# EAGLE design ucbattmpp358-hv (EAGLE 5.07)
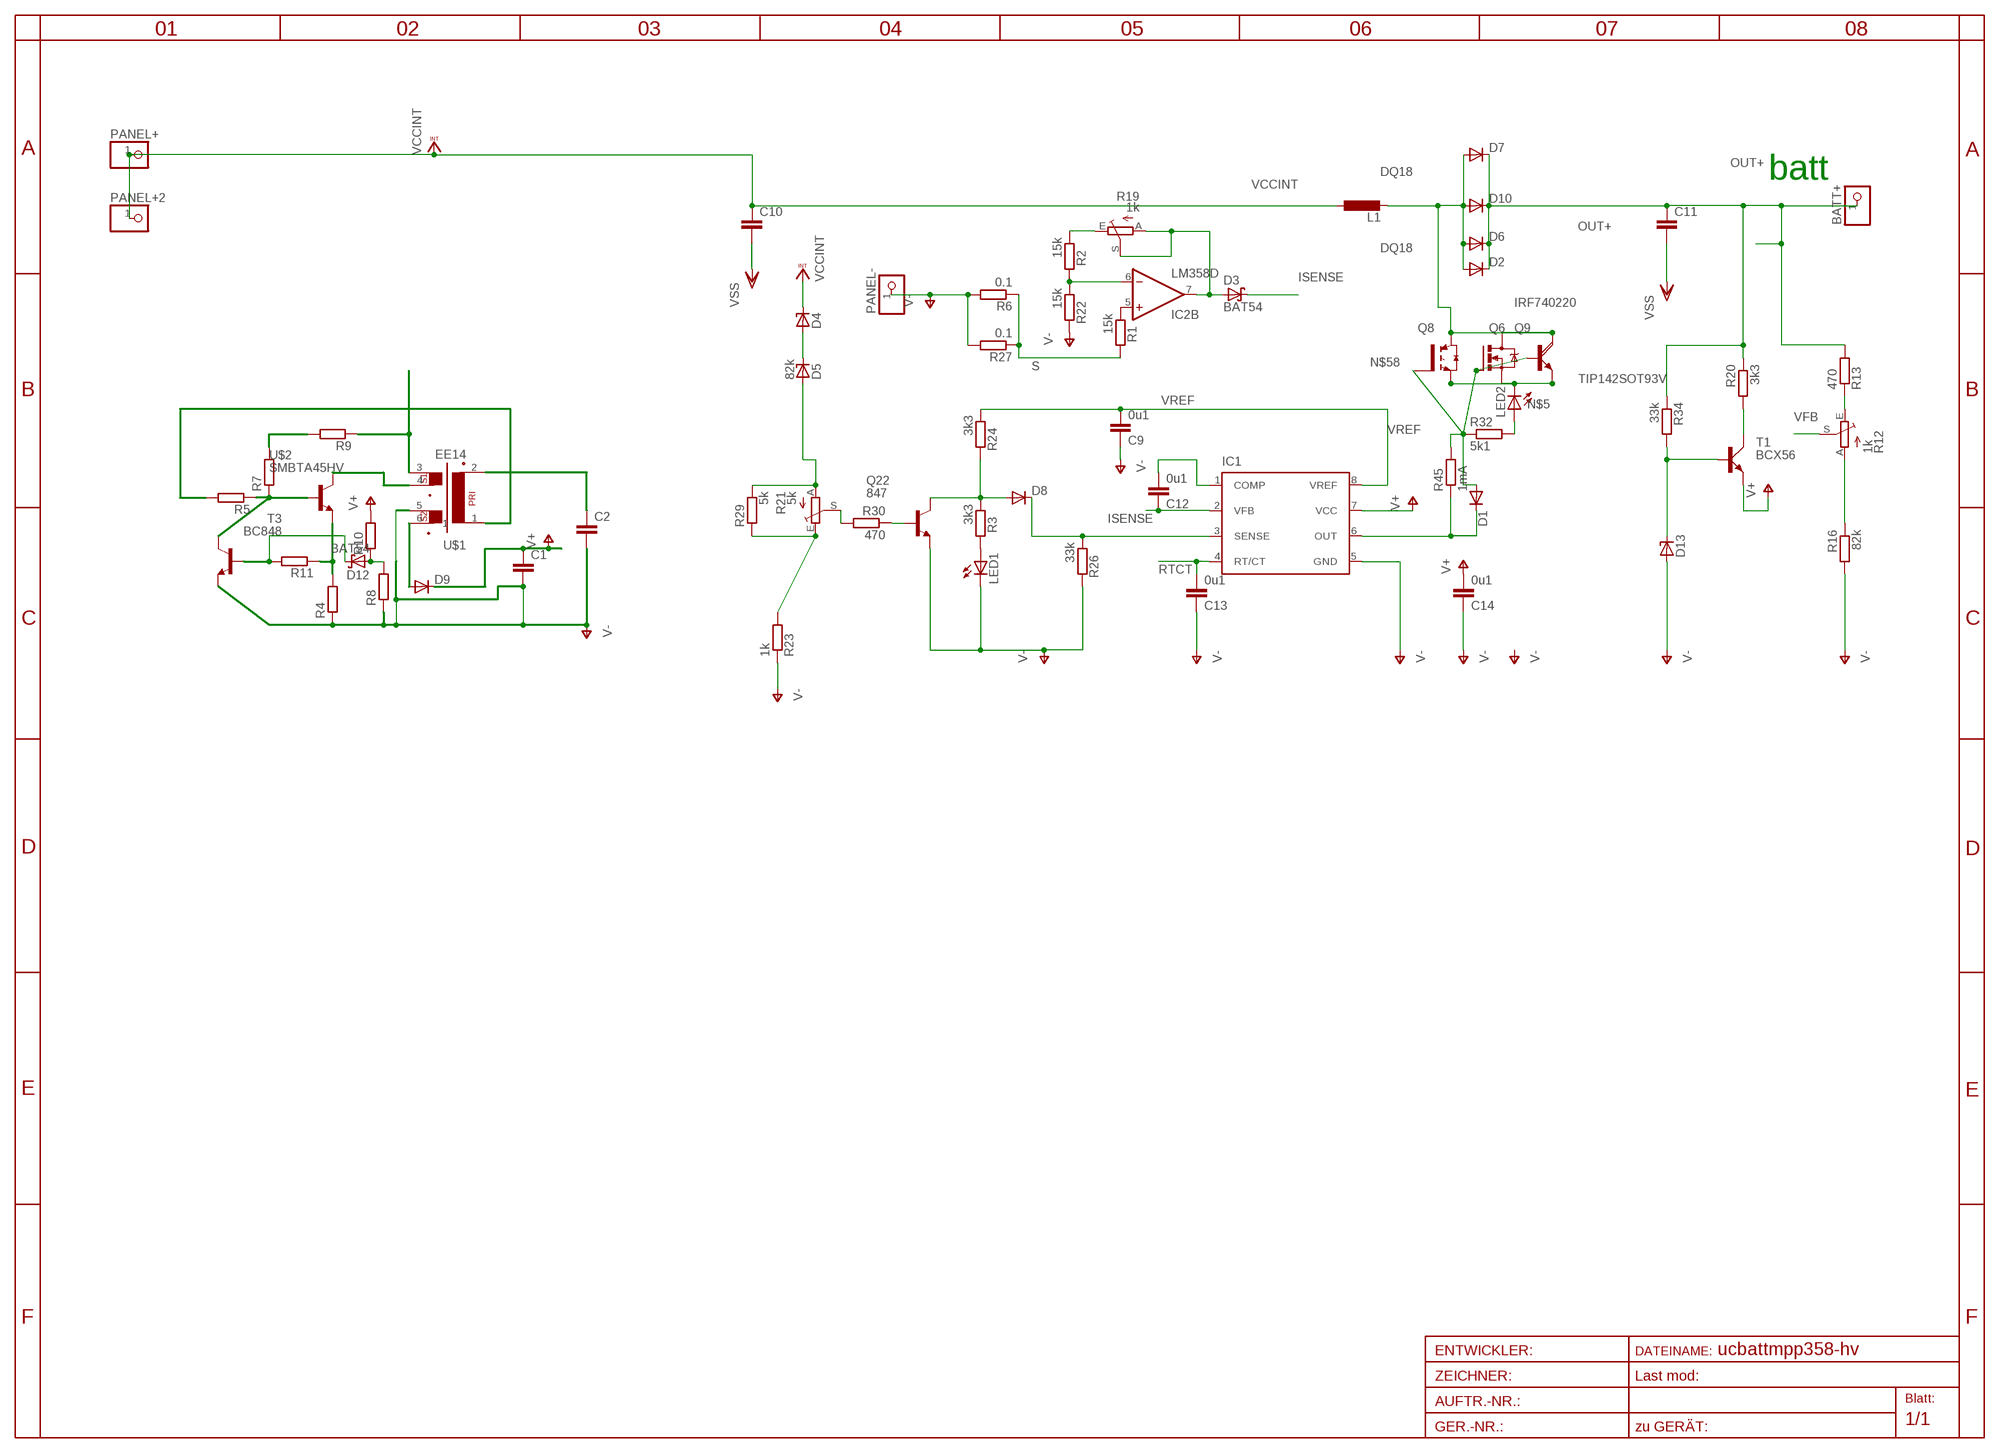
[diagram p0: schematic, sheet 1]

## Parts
BATT+  PINHD-1X12MM3  [1X2MM3]
C1  C-EUC1206  [C1206]
C2  C-EUC0805  [C0805]
C9  0u1  C-EUC1206  [C1206]
C10  C-EU075-052X106  [C075-052X106]
C11  C-EU075-052X106  [C075-052X106]
C12  0u1  C-EUC0805  [C0805]
C13  0u1  C-EUC1206  [C1206]
C14  0u1  C-EUC1206  [C1206]
D1  DIODE-MINIMELF  [MINIMELF]
D2  DIODE-SMC  [SMC]
D3  BAT54  [SOT23]
D4  ZENER-DIODESOD80C  [SOD80C]
D5  82k  ZENER-DIODESOD80C  [SOD80C]
D6  DIODE-SMC  [SMC]
D7  DIODE-SMC  [SMC]
D8  DIODE-MINIMELF  [MINIMELF]
D9  DIODE-SMA-DO214  [SMA-DO214AC]
D10  DIODE-SMC  [SMC]
D12  BAT54  [SOT23]
D13  ZENER-DIODESOD80C  [SOD80C]
IC1  UC1843D8  [SO-08]
IC2  LM358D  [SO08]
L1  L-EUOPEN6  [OPEN6_3]
LED1  LEDCHIPLED_1206  [CHIPLED_1206]
LED2  LEDCHIPLED_1206  [CHIPLED_1206]
PANEL+  PINHD-1X11MM6  [1X1MM8]
PANEL+2  PINHD-1X12MM3  [1X2MM3]
PANEL-  PINHD-1X12MM3  [1X2MM3]
Q6  IRF740220  [TO220BV]
Q8  IRG4BC15UD-S  [D2PACK]
Q9  TIP142SOT93V  [SOT93V]
Q22  847  BC847ASMD  [SOT23]
R1  15k  R-EU_R0805  [R0805]
R2  15k  R-EU_R0805  [R0805]
R3  3k3  R-EU_R0805  [R0805]
R4  R-EU_R0805  [R0805]
R5  R-EU_R0805  [R0805]
R6  0.1  R-EU_0207/10  [0207/10]
R7  R-EU_R1206  [R1206]
R8  R-EU_R0805  [R0805]
R9  R-EU_R1206  [R1206]
R10  R-EU_R0805  [R0805]
R11  R-EU_R0805  [R0805]
R12  1k  TRIM_EU-S64W  [S64W]
R13  470  R-EU_R0805  [R0805]
R16  82k  R-EU_R0805  [R0805]
R19  1k  TRIM_EU-S64W  [S64W]
R20  3k3  R-EU_R0805  [R0805]
R21  5k  TRIM_EU-S64W  [S64W]
R22  15k  R-EU_R0805  [R0805]
R23  1k  R-EU_R0805  [R0805]
R24  3k3  R-EU_R0805  [R0805]
R26  33k  R-EU_R0805  [R0805]
R27  0.1  R-EU_R3216  [R3216]
R29  5k  R-EU_R0805  [R0805]
R30  470  R-EU_R0805  [R0805]
R32  5k1  R-EU_R0805  [R0805]
R34  33k  R-EU_R0805  [R0805]
R45  1mA  R-EU_R0805  [R0805]
T1  BCX56  [SOT223]
T3  BC848  [SOT23]
U$1  EE14  [EE14]
U$2  SMBTA45HV  [SOT23HV]

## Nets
A: D9.A U$1.6
B1C2: R5.1 R7.1 T3.C U$2.1(B)
C1: U$1.4 U$2.3(C)
DQ18: D2.A D6.A D7.A D10.A L1.2 Q6.D Q8.2(C) Q9.C
EB: R4.2 R11.1 U$2.2(E)
ISENSE: D3.3(C) D8.C IC1.3(SENSE) R26.1
N$1: IC2.5(B:+IN) R1.1
N$2: R2.1 R19.E
N$3: Q22.1(B) R30.1
N$4: LED1.A R3.2
N$5: LED2.A R32.2
N$6: R5.2 U$1.1
N$7: C2.1 U$1.2
N$8: R7.2 R9.2
N$9: D12.3(C) R11.2 T3.B
N$10: D12.1(A) R8.2 R10.1
N$18: C12.2 IC1.1(COMP)
N$21: R12.A R16.1
N$22: D3.1(A) IC2.7(B:OUT) R19.A R19.S
N$23: R20.2 T1.2(C)
N$25: D1.C IC1.6(OUT) R45.1
N$26: D13.C R34.2 T1.1(B)
N$27: IC2.6(B:-IN) R2.2 R22.1
N$30: D4.A D5.C
N$32: D5.A R21.A R29.1
N$34: R21.E R23.2 R29.2
N$37: R12.E R13.1
N$58: D1.A Q6.G Q8.1(G) Q9.B R32.1 R45.2
N$71: D8.A Q22.3(C) R3.1 R24.2
OUT+: BATT+.1 C11.1 D2.C D6.C D7.C D10.C R9.1 R13.2 R20.1 R34.1 U$1.3
PRB1: R21.S R30.2
RTCT: C13.2 IC1.4(RT/CT)
S: LED2.C Q6.S Q8.3(E) Q9.E R1.2 R6.1 R27.1
V+: C1.1 C14.2 D9.K(C) IC1.7(VCC) R10.2 T1.3(E)
V-: C1.2 C2.2 C9.1 C10.2 C11.2 C13.1 C14.1 D13.A IC1.5(GND) LED1.C PANEL-.1 Q22.2(E) R4.1 R6.2 R8.1 R16.2 R22.2 R23.1 R26.2 R27.2 T3.E U$1.5 ; supply symbol labelled VSS
VCCINT: C10.1 D4.C L1.1 PANEL+2.1 PANEL+.1
VFB: C12.1 IC1.2(VFB) R12.S
VREF: C9.2 IC1.8(VREF) R24.1
Unconnected: IC2.1(A:OUT) IC2.2(A:-IN) IC2.3(A:+IN)

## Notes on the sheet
- batt

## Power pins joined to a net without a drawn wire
V+: IC2.8(P:V+)
V-: IC2.4(P:V-)

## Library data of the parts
BATT+ PANEL+ PANEL+2 PANEL- = pinhead:PINHD-1X1: PIN HEADER
C1 C2 C9-C14 = rcl:C-EU: CAPACITOR, European symbol
D1 D2 D6-D10 = diode:DIODE-: DIODE
D3 D12 = diode:BAT54: Schottky Diodes
D4 D5 D13 = diode:ZENER-DIODE: Z-Diode
IC1 = texas:UC1843D8: PULSE WIDTH MODULATOR
IC2 = linear:LM358: OP AMP also LM158; LM258; LM2904 Source: http://cache.national.com/ds/LM/LM158.pdf
L1 = rcl:L-EU: INDUCTOR, European symbol
LED1 LED2 = led:LED: LED
Q6 = transistor-power:IRF740: N-CHANNEL MOS FET
Q8 = transistor-power:IRG4BC15UD-: INSULATED GATE BIPOLAR TRANSISTOR WITH ULTRAFAST SOFT RECOVERY DIODE
Q9 = transistor-power:TIP142: NPN DARLINGTON TRANSISTOR
Q22 = transistor-npn:BC847*: NPN Transistor
R1-R11 R13 R16 R20 R22-R24 R26 R27 R29 R30 R34 = rcl:R-EU_: RESISTOR, European symbol
R12 R19 R21 = pot:TRIM_EU-: POTENTIOMETER
R32 R45 = rcl-2:R-EU_: RESISTOR, European symbol
T1 = transistor-power:BCX56
T3 = transistor:BC848: NPN TRANSISTOR
U$1 = trafo:EE14
U$2 = transistor-npn:SMBTA45

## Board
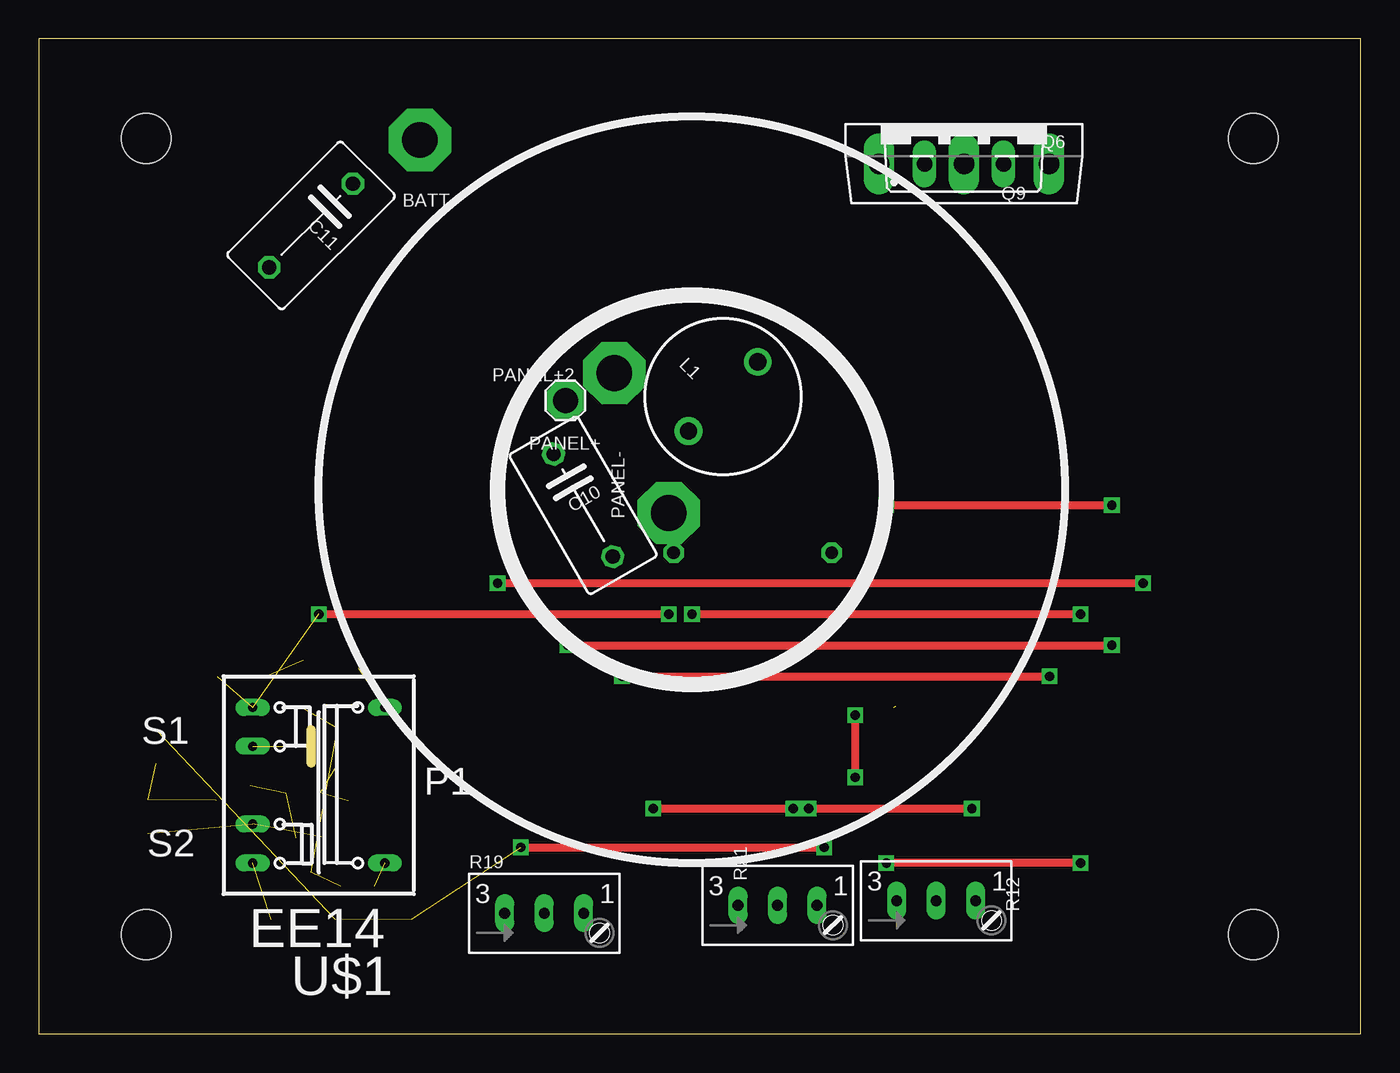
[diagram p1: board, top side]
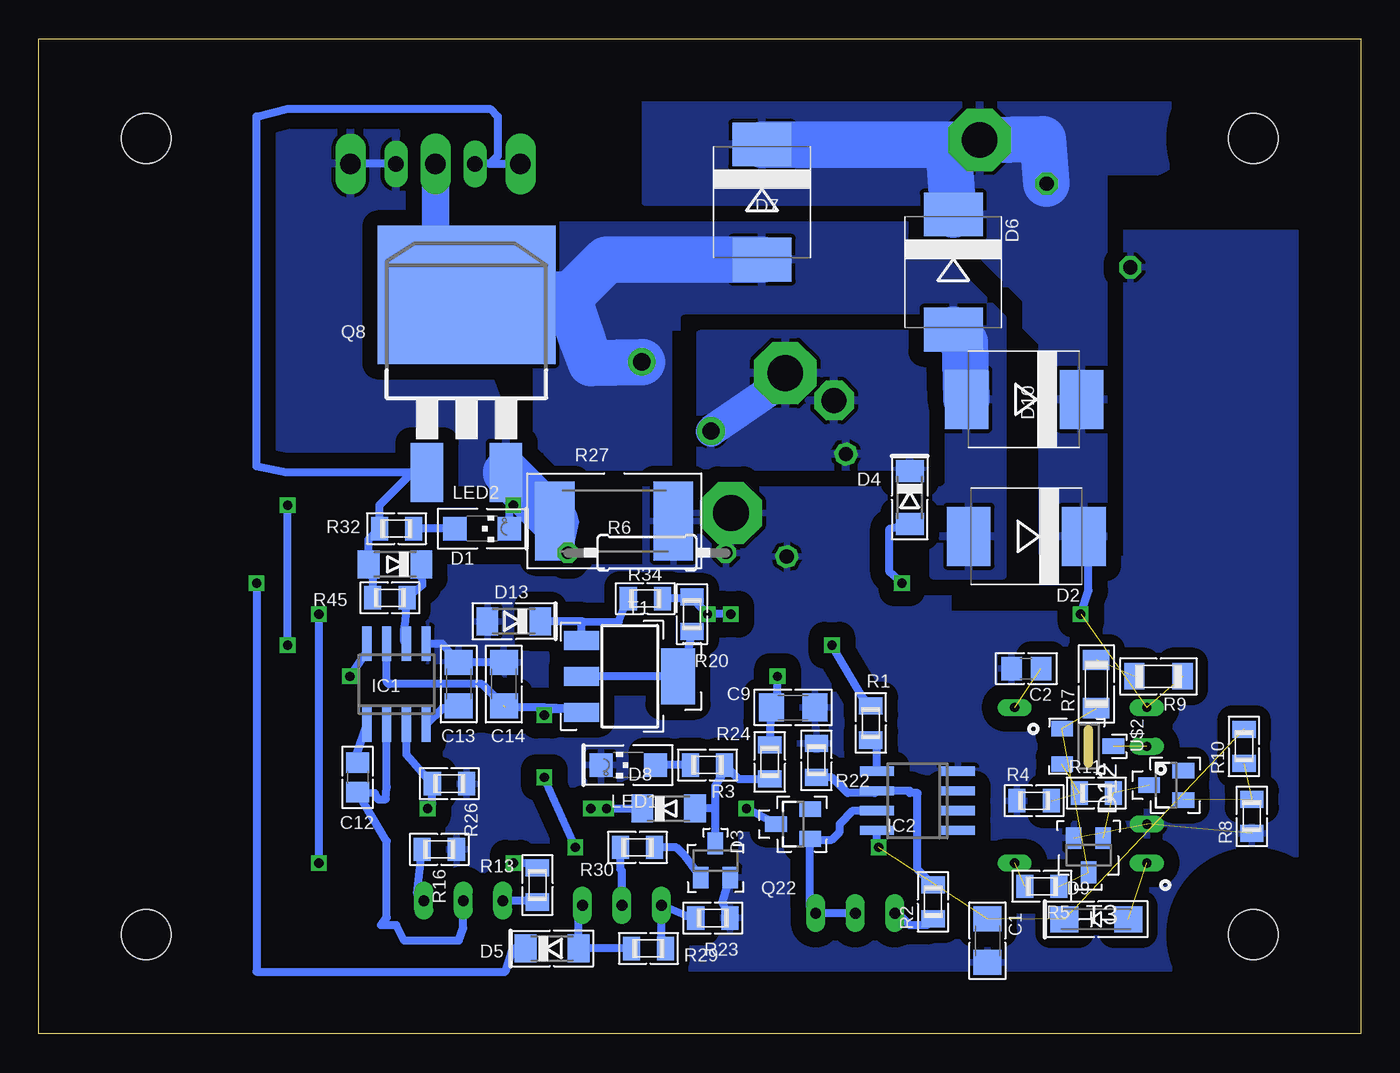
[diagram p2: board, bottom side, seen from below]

Size 85 x 64 mm. Coordinates in mm from the lower left corner, seen from the top.
Outline: 0,0 85,0 85,64 0,64 0,0
Copper layers (1*16): Top 0.035mm / dielectric 1.5mm / Bottom 0.035mm
Design rules "default *": minimum track width 10mil, minimum drill 24mil, track to track 8mil, track to pad 8mil, pad to pad 8mil, via to via 8mil, smd to smd 8mil, copper to edge 4mm, drill to drill 8mil, minimum pad ring 10mil, minimum via ring 8mil, stop-mask expansion 4mil, vias tented up to drill 0mil, thermal gap 10mil
Holes 3.2 mm at 6.9,57.6 6.9,6.4 78.1,6.4 78.1,57.6

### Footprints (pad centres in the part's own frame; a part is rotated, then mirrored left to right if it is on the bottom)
1X2MM3 = drill 2.3 pad 4 octagon: 1 0,0
C1206 = smd 1.6 x 1.8: 1 -1.4,0; 2 1.4,0
C0805 = smd 1.3 x 1.5: 1 -0.95,0; 2 0.95,0
C075-052X106 = drill 0.914 octagon: 1 -3.81,0; 2 3.81,0
MINIMELF = smd 1.4 x 1.8: A 1.7,0; C -1.7,0
SMC = smd 2.8 x 3.8: A 3.7,0; C -3.7,0
SOT23 = smd 1 x 1.4: 1 -0.95,-1.1; 2 0.95,-1.1; 3 0,1.1
SOD80C = smd 1.4 x 1.8: A 1.7,0; C -1.7,0
SMA-DO214AC = smd 1.8 x 1.7: A 2.05,-0.127; K -2.05,-0.127
SO-08 = smd 0.6 x 2.2: 1 -1.905,-2.6; 2 -0.635,-2.6; 3 0.635,-2.6; 4 1.905,-2.6; 5 1.905,2.6; 6 0.635,2.6; 7 -0.635,2.6; 8 -1.905,2.6
SO08 = smd 0.6 x 2.2: 1 -1.905,-2.6; 2 -0.635,-2.6; 3 0.635,-2.6; 4 1.905,-2.6; 5 1.905,2.6; 6 0.635,2.6; 7 -0.635,2.6; 8 -1.905,2.6
OPEN6_3 = drill 1.1 pad 1.778 round: 1 -3.15,0; 2 3.15,0
CHIPLED_1206 = smd 1.5 x 1.5: A 0,-1.75; C 0,1.75
1X1MM8 = drill 1.6 pad 2.54 octagon: 1 0,0
TO220BV = drill 1.016 long: D 0,-2.54; G -2.54,-2.54; S 2.54,-2.54
D2PACK = smd 2.083 x 3.81: 1 -2.54,-8.89; 3 2.54,-8.89 | smd 11.43 x 8.89: 2 0,2.54
SOT93V = drill 1.3 pad 1.676 long: B -5.461,-2.54; C 0,-2.54; E 5.461,-2.54
R0805 = smd 1.1 x 1.5: 1 -1.1,0; 2 1.1,0
0207/10 = drill 0.813 octagon: 1 -5.08,0; 2 5.08,0
R1206 = smd 1.3 x 1.7: 1 -1.55,0; 2 1.55,0
S64W = drill 0.7 long: A 2.54,1.27; E -2.54,1.27; S 0,1.27
R3216 = smd 2.54 x 5.08: 1 -3.81,0; 2 3.81,0
SOT223 = smd 1.219 x 2.235: 1 -2.311,-3.099; 2 0,-3.099; 3 2.311,-3.099 | smd 3.6 x 2.2: 4 0,3.099
SOT23' = smd 1 x 1.4: B -0.95,-1.1; C 0,1.1; E 0.95,-1.1
EE14 = drill 0.6 pad 1 long: 1 4.25,-5; 2 4.25,5; 3 -4.25,5 | drill 0.6 pad 1.016 long: 4 -4.25,2.5; 5 -4.25,-2.5; 6 -4.25,-5
SOT23HV = smd 1 x 1.4: 1 -1.15,-1.7; 2 1.15,-1.7; 3 0,1.6

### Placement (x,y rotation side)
BATT+  24.5,57.5 0 top
C1  24,6 270 bottom
C2  21.5,23.5 180 bottom
C9  36.5,21 180 bottom
C10  35,34 300 top
C11  17.5,52 225 top
C12  64.5,16.5 90 bottom
C13  58,22.5 270 bottom
C14  55.1,22.5 270 bottom
D1  62.1,30.2 180 bottom
D2  21.5,32 180 bottom
D3  36.5,13.5 90 bottom
D4  29,34.5 270 bottom
D5  52,5.5 0 bottom
D6  26.2,49 270 bottom
D7  38.5,53.5 270 bottom
D8  44.5,14.5 0 bottom
D9  17,7.5 0 bottom
D10  21.65,40.81 180 bottom
D12  12.5,16 90 bottom
D13  54.46,26.55 180 bottom
IC1  62,22.5 0 bottom
IC2  28.5,15 90 bottom
L1  44,41 45 top
LED1  47.1,17.3 90 bottom
LED2  56.5,32.5 270 bottom
PANEL+  33.86,40.74 0 top
PANEL+2  37,42.5 0 top
PANEL-  40.5,33.5 90 top
Q6  59.5,58.5 0 top
Q8  57.5,45 0 bottom
Q9  59.5,58.5 0 top
Q22  41.49,11.16 0 bottom
R1  31.5,20 90 bottom
R2  27.5,8.5 90 bottom
R3  42,17.3 180 bottom
R4  21,15 0 bottom
R5  20.5,9.5 180 bottom
R6  45.9,30.95 0 bottom
R7  17,22.5 90 bottom
R8  7,14 90 bottom
R9  13,23 180 bottom
R10  7.5,18.5 90 bottom
R11  17,15.5 0 bottom
R12  57.7,7.3 0 top
R13  52.94,9.58 90 bottom
R16  59.25,11.88 0 bottom
R19  32.5,6.5 0 top
R20  43,27 270 bottom
R21  47.51,7 0 top
R22  35,17.6 90 bottom
R23  41.66,7.46 180 bottom
R24  38,17.5 270 bottom
R26  58.6,16.1 0 bottom
R27  48,33 0 bottom
R29  45.8,5.5 0 bottom
R30  46.5,12 180 bottom
R32  62,32.5 0 bottom
R34  46,28 180 bottom
R45  62.43,28.05 180 bottom
T1  47,23 270 bottom
T3  BC848  [SOT23']  17.5,11.5 180 bottom
U$1  18,16 0 top
U$2  17.5,18.5 270 bottom

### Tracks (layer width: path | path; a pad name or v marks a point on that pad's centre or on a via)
A  (1 unrouted)
B1C2  (3 unrouted)
C1  (1 unrouted)
DQ18
  Bottom 1.778: 59.5,48.04 Q9.C
  Bottom 2.54: Q8.2 59.5,48.04
  Bottom 3: Q8.2 51.04,47.54 50.97,47.34 | 50.97,47.34 50,44.5 49.5,43.15 L1.2 | D7.A 48.51,49.8 50.97,47.34 | D6.A 25.8,44.8 25.45,44.45 D10.A
  pour Bottom (isolate 1, rank 2): 29,52 53,52 53,36.5 44.5,36.5 44.5,45.5 27.5,45.5 27.5,29.5 23,29.5 23,46
EB  (2 unrouted)
ISENSE  (via drill 0.6)
  Top 0.5: v49.5,14.5 v60,14.5 | v39.5,14.5 v48.5,14.5
  Bottom 0.5: IC1.3 61.37,17.96 R26.1 59.7,14.8 v60,14.5 | v49.5,14.5 v48.5,14.5 D8.C | D3.3 v39.5,14.5
N$1
  Bottom 0.5: IC2.5 31.1,18.5 R1.1
N$2
  Bottom 0.5: R19.E 29.77,7.77 29,7 27.9,7 R2.1
N$3
  Bottom 0.5: Q22.1 43.56,11.56 44,12 R30.1
N$4
  Bottom 0.5: R3.2 LED1.A
N$5
  Bottom 0.5: LED2.A R32.2
N$6  (1 unrouted)
N$7  (1 unrouted)
N$8  (1 unrouted)
N$9  (2 unrouted)
N$10  (2 unrouted)
N$18
  Bottom 0.5: IC1.1 64.6,17.9 64.5,18 C12.2
N$21
  Bottom 0.5: R12.A 60.67,9.01 R16.1
N$22
  Bottom 0.5: IC2.7 32.63,14.37 33.5,13.5 33.5,13 34,12.5 35.35,12.5 D3.1 35.4,8.13 R19.A R19.S
N$23
  Bottom 0.5: T1.2 43.6,23 R20.2
N$25
  Bottom 0.5: IC1.6 61.5,25.23 61.5,26 61.43,26.57 R45.1 60.33,28.87 D1.C
N$26
  Bottom 0.5: R34.2 47.71,26.5 49.99,26.52 | 49.99,26.52 D13.C | T1.1 50.1,26.42 49.99,26.52
N$27
  Bottom 0.5: R2.2 28.5,10.6 28.5,15.5 29,15.5 29,15.63 IC2.6 31.23,15.5 33,15.5 34,16.5 R22.1
N$30  (via drill 0.6)
  Top 0.5: v29.5,29 v71,29
  Bottom 0.5: D5.C 54.5,5.5 55,4 71,4 v71,29 | D4.A 30.3,32.5 30.3,29.7 v29.5,29
N$32
  Bottom 0.5: R29.1 D5.A 50.3,8.34 R21.A
N$34
  Bottom 0.5: R29.2 44.5,5.5 45,6 45,8.56 R21.E 43.4,7.59 R23.2
N$37
  Bottom 0.5: R13.1 53.03,8.57 R12.E
N$58
  Bottom 0.5: 56,55.96 Q9.B | 56,55.96 Q6.G | R45.2 63.53,29.43 D1.A 63.8,31.8 R32.1 63.1,34.01 61,36.11 | 61,36.11 Q8.1 | 61,36.11 69.11,36.11 71,36.5 71,59 69,59.5 56,59.5 55.5,59 55.5,56.46 56,55.96
N$71
  Bottom 0.5: Q22.3 41.49,14.5 | 41.49,14.5 41.49,15.96 40.9,16.87 R3.1 40,16.4 R24.2 | 41.49,14.5 D8.A
OUT+  (via drill 0.6)  (2 unrouted)
  Top 0.5: v67,11 v54.5,11 | v18,27 v40.5,27 | v42,27 v67,27
  Bottom 0.5: R34.1 43,28 R20.1 42.5,27.5 v42,27 v40.5,27 | v67,27 v67,11 | v54.5,11 53.26,11 R13.2 | 17.5,32 17.5,28.5 v18,27
  Bottom 3: C11.1 20.44,57.56 BATT+.1 24.8,57.2 26.5,57.2 | 26.5,57.2 D7.C | 26.5,57.2 D6.C
  pour Bottom (isolate 1, rank 3): 12,56 12,60.5 46,60.5 46,53.5 29.5,53.5 20.5,44.5 20.5,31 20,30.5 16.5,30.5 16.5,55.5 13,55.5
PRB1
  Bottom 0.5: R30.2 47.6,10.6 47.5,10.5 47.5,8.6 R21.S
RTCT
  Bottom 0.5: IC1.4 59.05,20.95 C13.2
S  (via drill 0.6)
  Top 0.5: v69,34 v54.5,34 | v34,25 v69,25
  Bottom 0.5: Q6.S Q9.E | Q8.3 54.61,36.11 54,35.5 54.5,35.5 54,35 54.5,34.5 v54.5,34 54.75,33.75 LED2.C | v69,25 v69,34 | v34,25 32,21.6 R1.2 | R27.1 50.53,33 R6.1
  Bottom 3: R27.1 51.85,33 Q8.3
  pour Bottom (isolate 1): 62,58 70.5,58 71,57.5 71,35.5 53.5,35.5
V+  (via drill 0.6)  (4 unrouted)
  Top 0.5: v31,12 v50.5,12 | v52.5,16.5 v52.5,20.5
  Bottom 0.5: IC2.8 31.1,12.1 v31,12 | v50.5,12 v52.5,16.5 | IC1.7 62.63,22.64 62.5,22.5 56.5,22.5 55,21 52.41,21 50.94,20.94 | 50.94,20.94 T1.3 | v52.5,20.5 52,20.88 50.94,20.94
V-  (2 unrouted)
  Bottom 0.5: C14.1 C13.1 59.05,25.1 IC1.5 | R23.1 41.04,8.47 Q22.2
  pour Bottom (isolate 1, rank 4): 68.5,1 2.5,1.5 2.5,51.5 17,51.5 16.5,27 26.5,27 26.5,35.5 46,36 46,30 66.5,30
VCCINT
  Bottom 2: 37,42.05 L1.1
  Bottom 3: PANEL+2.1 37,42.05
  pour Bottom (isolate 1): 28,45 42.5,45 42.5,36.5 28,36.5
VFB
  Bottom 0.5: IC1.2 62.63,15.87 62.7,15.1 63.2,15.1 63.4,15.5 C12.1 62.63,12.4 62.63,7.5 63,7 62,7 61.5,6 58,6 57.7,6.79 R12.S
VREF  (via drill 0.6)
  Top 0.5: v37.5,23 v65,23
  Bottom 0.5: R24.1 C9.2 37.5,21.45 v37.5,23 | IC1.8 63.91,24.59 v65,23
